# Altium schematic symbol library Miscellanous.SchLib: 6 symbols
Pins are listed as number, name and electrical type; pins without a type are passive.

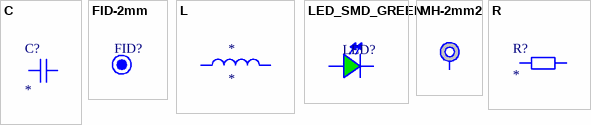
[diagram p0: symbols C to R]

## C
designator C?
footprint CAP_SMD (MLCC Capacitor, 0508 Case Size)
pins: 1 Pin 1, 2 Pin 2

## FID-2mm
designator FID?  (value not drawn)  (graphical)
footprint fid-2mm

## L
designator *
pins: 1 Pin 1, 2 Pin 2

## LED_SMD_GREEN
designator LED?  (value not drawn)
footprint LED_0805_GREEN (Footprint for 0805 Case Size LED)
pins: 1 A, 2 C

## MH-2mm2
designator MH?, comment Mounting hole, non-plated, 2.2mm  (value not drawn)  (no BOM)
footprint MH-2mm2 (2.2mm Mounting hole, non plated)
pins: 1 Pin1 (power)

## R
designator R?
footprint RES_0805 (SMD Resistor, 0805 Case Size)
pins: 1 Pin 1, 2 Pin 2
